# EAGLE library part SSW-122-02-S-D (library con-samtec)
THROUGH-HOLE .025" SQ POST SOCKET Source: Samtec SSW.pdf
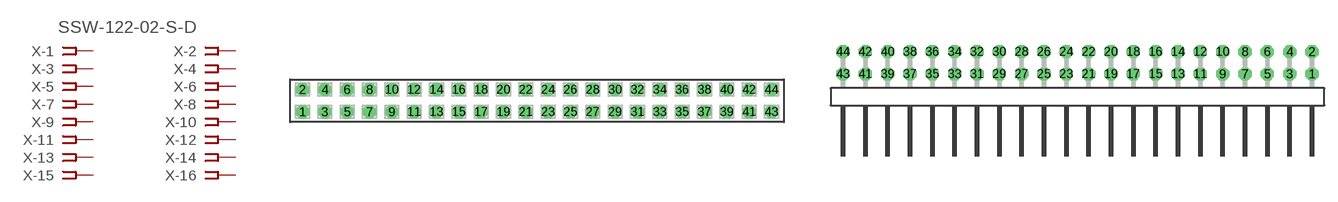
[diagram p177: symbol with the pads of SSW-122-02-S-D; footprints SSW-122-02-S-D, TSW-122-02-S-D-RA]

Designator prefix X; gates -1=FPINV -2=FPIN -3=FPIN -4=FPIN -5=FPIN -6=FPIN -7=FPIN -8=FPIN -9=FPIN -10=FPIN -11=FPIN -12=FPIN -13=FPIN -14=FPIN -15=FPIN -16=FPIN -17=FPIN -18=FPIN -19=FPIN -20=FPIN -21=FPIN -22=FPIN -23=FPIN -24=FPIN -25=FPIN -26=FPIN -27=FPIN -28=FPIN -29=FPIN -30=FPIN -31=FPIN -32=FPIN -33=FPIN -34=FPIN -35=FPIN -36=FPIN -37=FPIN -38=FPIN -39=FPIN -40=FPIN -41=FPIN -42=FPIN -43=FPIN -44=FPIN

## SSW-122-02-S-D (MPN: SSW-122-02-S-D; OC_FARNELL: unknown; OC_NEWARK: 11P9673)  [SSW-122-02-S-D]
1  -1:1  pas
2  -2:1  pas
3  -3:1  pas
4  -4:1  pas
5  -5:1  pas
6  -6:1  pas
7  -7:1  pas
8  -8:1  pas
9  -9:1  pas
10  -10:1  pas
11  -11:1  pas
12  -12:1  pas
13  -13:1  pas
14  -14:1  pas
15  -15:1  pas
16  -16:1  pas
17  -17:1  pas
18  -18:1  pas
19  -19:1  pas
20  -20:1  pas
21  -21:1  pas
22  -22:1  pas
23  -23:1  pas
24  -24:1  pas
25  -25:1  pas
26  -26:1  pas
27  -27:1  pas
28  -28:1  pas
29  -29:1  pas
30  -30:1  pas
31  -31:1  pas
32  -32:1  pas
33  -33:1  pas
34  -34:1  pas
35  -35:1  pas
36  -36:1  pas
37  -37:1  pas
38  -38:1  pas
39  -39:1  pas
40  -40:1  pas
41  -41:1  pas
42  -42:1  pas
43  -43:1  pas
44  -44:1  pas

## SSW-122-02-S-D-RA (MPN: SSW-122-02-S-D-RA; OC_FARNELL: unknown; OC_NEWARK: 11P9674)  [TSW-122-02-S-D-RA]
Pads as for SSW-122-02-S-D

## Footprint SSW-122-02-S-D (pad centres in mm)
THROUGH-HOLE .025" SQ POST SOCKET Source: Samtec SSW.pdf
drill 1 pad 1.5 octagon: 1 -26.67,-1.27; 2 -26.67,1.27; 3 -24.13,-1.27; 4 -24.13,1.27; 5 -21.59,-1.27; 6 -21.59,1.27; 7 -19.05,-1.27; 8 -19.05,1.27; 9 -16.51,-1.27; 10 -16.51,1.27; 11 -13.97,-1.27; 12 -13.97,1.27; 13 -11.43,-1.27; 14 -11.43,1.27; 15 -8.89,-1.27; 16 -8.89,1.27; 17 -6.35,-1.27; 18 -6.35,1.27; 19 -3.81,-1.27; 20 -3.81,1.27; 21 -1.27,-1.27; 22 -1.27,1.27; 23 1.27,-1.27; 24 1.27,1.27; 25 3.81,-1.27; 26 3.81,1.27; 27 6.35,-1.27; 28 6.35,1.27; 29 8.89,-1.27; 30 8.89,1.27; 31 11.43,-1.27; 32 11.43,1.27; 33 13.97,-1.27; 34 13.97,1.27; 35 16.51,-1.27; 36 16.51,1.27; 37 19.05,-1.27; 38 19.05,1.27; 39 21.59,-1.27; 40 21.59,1.27; 41 24.13,-1.27; 42 24.13,1.27; 43 26.67,-1.27; 44 26.67,1.27

## Footprint TSW-122-02-S-D-RA (pad centres in mm)
THROUGH-HOLE .025" SQ POST HEADER Source: Samtec TSW.pdf
drill 1 pad 1.5 octagon: 1 26.67,1.524; 2 26.67,4.064; 3 24.13,1.524; 4 24.13,4.064; 5 21.59,1.524; 6 21.59,4.064; 7 19.05,1.524; 8 19.05,4.064; 9 16.51,1.524; 10 16.51,4.064; 11 13.97,1.524; 12 13.97,4.064; 13 11.43,1.524; 14 11.43,4.064; 15 8.89,1.524; 16 8.89,4.064; 17 6.35,1.524; 18 6.35,4.064; 19 3.81,1.524; 20 3.81,4.064; 21 1.27,1.524; 22 1.27,4.064; 23 -1.27,1.524; 24 -1.27,4.064; 25 -3.81,1.524; 26 -3.81,4.064; 27 -6.35,1.524; 28 -6.35,4.064; 29 -8.89,1.524; 30 -8.89,4.064; 31 -11.43,1.524; 32 -11.43,4.064; 33 -13.97,1.524; 34 -13.97,4.064; 35 -16.51,1.524; 36 -16.51,4.064; 37 -19.05,1.524; 38 -19.05,4.064; 39 -21.59,1.524; 40 -21.59,4.064; 41 -24.13,1.524; 42 -24.13,4.064; 43 -26.67,1.524; 44 -26.67,4.064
